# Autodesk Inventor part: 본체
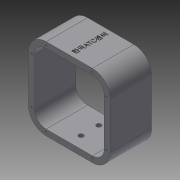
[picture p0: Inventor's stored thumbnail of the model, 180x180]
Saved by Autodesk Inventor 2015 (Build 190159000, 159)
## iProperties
Created: 2016-12
Part Number: 본체
Material: 알루미늄 6061
Document SubType Name: Modeling
Designer: mduedu
Density: 2.71 g/cm^3
Mass: 883.341 g
Surface Area: 772.714 cm^2
Volume: 325.956 cm^3
Appearance: 기본값
Author: mduedu
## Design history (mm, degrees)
sketch "스케치1"
  geometry: L1 (-46, 42)-(-46, -36); L2 (-16, 72)-(62, 72); L3 (92, 42)-(92, -36); L4 (62, -66)-(-16, -66); A1 r 30 centre (-16, -36) between (-46, -36) and (-16, -66); A2 r 30 centre (62, 42) between (92, 42) and (62, 72); A3 r 30 centre (62, -36) between (62, -66) and (92, -36); A4 r 30 centre (-16, 42) between (-16, 72) and (-46, 42); 1 further point
  constraints: 8 end point, 8 point on circle, 8 tangent, 4 centre point, 3 equal radius, 1 horizontal, 1 perpendicular, 1 vertical
  dimensions: "d83" = 30 radius of A2; "d84" = 92 distance from line of L3 point (0, 0); "d85" = 138 distance between parallel lines of L4 L2; "d86" = 46 distance from line of L1 point (0, 0); "d87" = 72 distance from line of point (0, 0) L2
extrude "돌출1" new body sketch "스케치1" stored distance "d3" = 70; taper "d4" = 0 deg
feature "쉘1" dims "d5" = 10
sketch "스케치10"
  geometry: L1 (78, 70)-(0, 70) reference; L2 (-30, 70)-(-30, 0) reference; 4 further points
  constraints: 1 coincident, 1 horizontal alignment, 1 midpoint, 1 vertical alignment, 1 other
  dimensions: "d88" = 35 distance of point (39, 35) point (39, 70) (derived); "d89" = 69 distance from line of point (39, 35) L2 (derived)
feature "엠보싱1" sketch "스케치10" dims "d61" = 0.5, "d62" = 0, "d83" = 30, "d84" = 92, "d85" = 138, "d86" = 46, "d87" = 72
sketch "스케치11"
  geometry: L1 (-36, -36)-(-36, 42) reference; L2 (-16, 62)-(62, 62) reference; L3 (82, 42)-(82, -36) reference; L4 (62, -56)-(-16, -56) reference; L5 (-16, -66)-(62, -66) reference; L6 (92, -36)-(92, 42) reference; L7 (62, 72)-(-16, 72) reference; L8 (-46, 42)-(-46, -36) reference; L9 (-16, 66)-(62, 66); L10 (86, 42)-(86, -36); L11 (62, -60)-(-16, -60); L12 (-40, -36)-(-40, 42); A1 r 20 centre (-16, -36) between (-36, -36) and (-16, -56) reference; A2 r 20 centre (-16, 42) between (-16, 62) and (-36, 42) reference; A3 r 20 centre (62, 42) between (82, 42) and (62, 62) reference; A4 r 20 centre (62, -36) between (62, -56) and (82, -36) reference; A5 r 30 centre (-16, -36) between (-46, -36) and (-16, -66) reference; A6 r 30 centre (62, -36) between (62, -66) and (92, -36) reference; A7 r 30 centre (62, 42) between (92, 42) and (62, 72) reference; A8 r 30 centre (-16, 42) between (-16, 72) and (-46, 42) reference; A9 r 24 centre (62, 42) between (86, 42) and (62, 66); A10 r 24 centre (62, -36) between (62, -60) and (86, -36); A11 r 24 centre (-16, -36) between (-40, -36) and (-16, -60); A12 r 24 centre (-16, 42) between (-16, 66) and (-40, 42); 8 further points
  constraints: 8 coincident, 8 end point, 8 point on circle, 4 centre point, 7 other
  dimensions: "d90" = 6 distance between parallel lines of L9 L7
hole "구멍3" sketch "스케치11" at (-16, 66), (-40, 42), (-40, -36), (-16, -60), (62, -60), (86, -36), (86, 42), (62, 66) diameter "d63" = 3.242; stored, may be unused: countersink angle "d67" = 90 deg, drill point angle "d69" = 120 deg; dims "d64" = 8.6, "d65" = 4, "d66" = 2, "d68" = 10.6
sketch "스케치12"
  geometry: L1 (16, -56)-(-62, -56) reference; L2 (-82, -36)-(-82, 42) reference; L3 (-62, 62)-(16, 62) reference; L4 (36, 42)-(36, -36) reference; L5 (46, -36)-(46, 42) reference; L6 (16, 72)-(-62, 72) reference; L7 (-92, 42)-(-92, -36) reference; L8 (-62, -66)-(16, -66) reference; L9 (-62, 66)-(16, 66); L10 (40, 42)-(40, -36); L11 (16, -60)-(-62, -60); L12 (-86, -36)-(-86, 42); A1 r 20 centre (16, -36) between (16, -56) and (36, -36) reference; A2 r 20 centre (-62, -36) between (-82, -36) and (-62, -56) reference; A3 r 20 centre (-62, 42) between (-62, 62) and (-82, 42) reference; A4 r 20 centre (16, 42) between (36, 42) and (16, 62) reference; A5 r 30 centre (16, -36) between (16, -66) and (46, -36) reference; A6 r 30 centre (16, 42) between (46, 42) and (16, 72) reference; A7 r 30 centre (-62, 42) between (-62, 72) and (-92, 42) reference; A8 r 30 centre (-62, -36) between (-92, -36) and (-62, -66) reference; A9 r 24 centre (16, 42) between (40, 42) and (16, 66); A10 r 24 centre (16, -36) between (16, -60) and (40, -36); A11 r 24 centre (-62, -36) between (-86, -36) and (-62, -60); A12 r 24 centre (-62, 42) between (-62, 66) and (-86, 42); 8 further points
  constraints: 8 coincident, 8 end point, 8 point on circle, 4 centre point, 7 other
  dimensions: "d91" = 6 distance between parallel lines of L9 L6
hole "구멍5" sketch "스케치12" at (-62, 66), (-86, 42), (-86, -36), (-62, -60), (16, -60), (40, -36), (40, 42), (16, 66) diameter "d70" = 3.242; stored, may be unused: countersink angle "d74" = 90 deg, drill point angle "d76" = 120 deg; dims "d71" = 8.6, "d72" = 4, "d73" = 2, "d75" = 10.6
sketch "스케치15"
  geometry: L1 (135.6, -35)-(-57.6, -35) reference; L2 (78, 0)-(0, 0) reference; L3 (0, -70)-(78, -70) reference; L4 (39, 0)-(39, -70); C1 r 4 at (39, -20); C2 r 4 at (39, -50); 1 further point
  constraints: 2 centre point, 2 end point, 2 midpoint, 1 point on line, 1 symmetric about line, 1 other
  dimensions: "d92" = 8 diameter of C1; "d93" = 15 distance from line of C1.centre L1
extrude "돌출6" cut sketch "스케치15" stored distance "d94" = 10; taper "d95" = 0 deg
node "솔리드1"
node "투영된 루프3"
node "투영된 루프4"
